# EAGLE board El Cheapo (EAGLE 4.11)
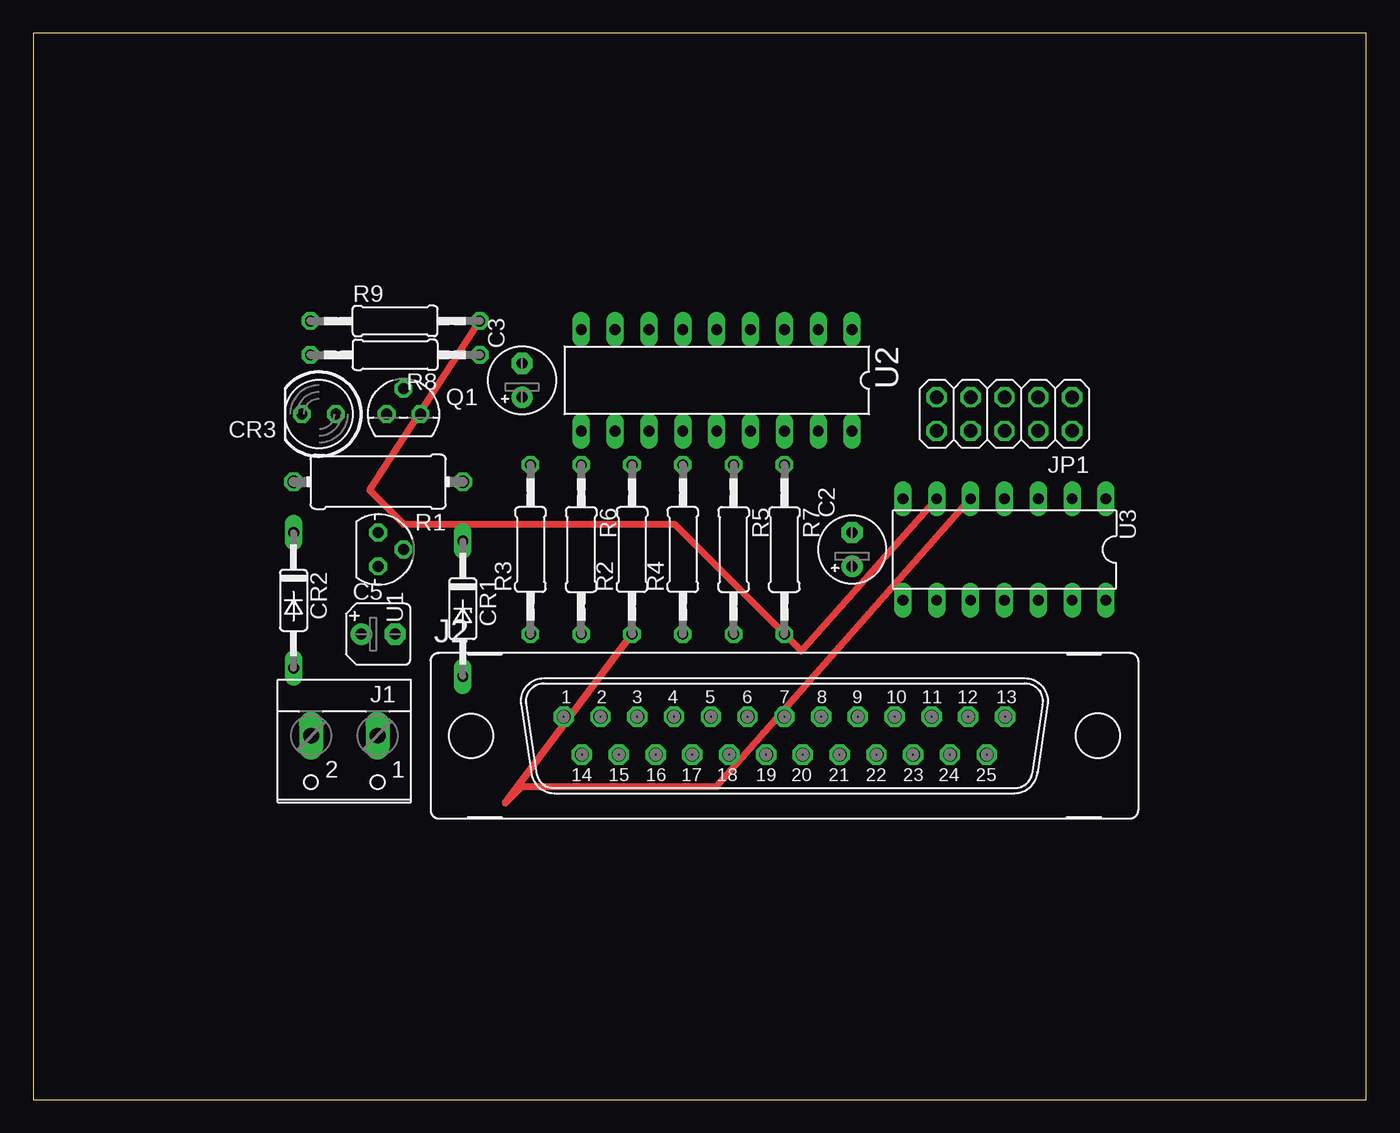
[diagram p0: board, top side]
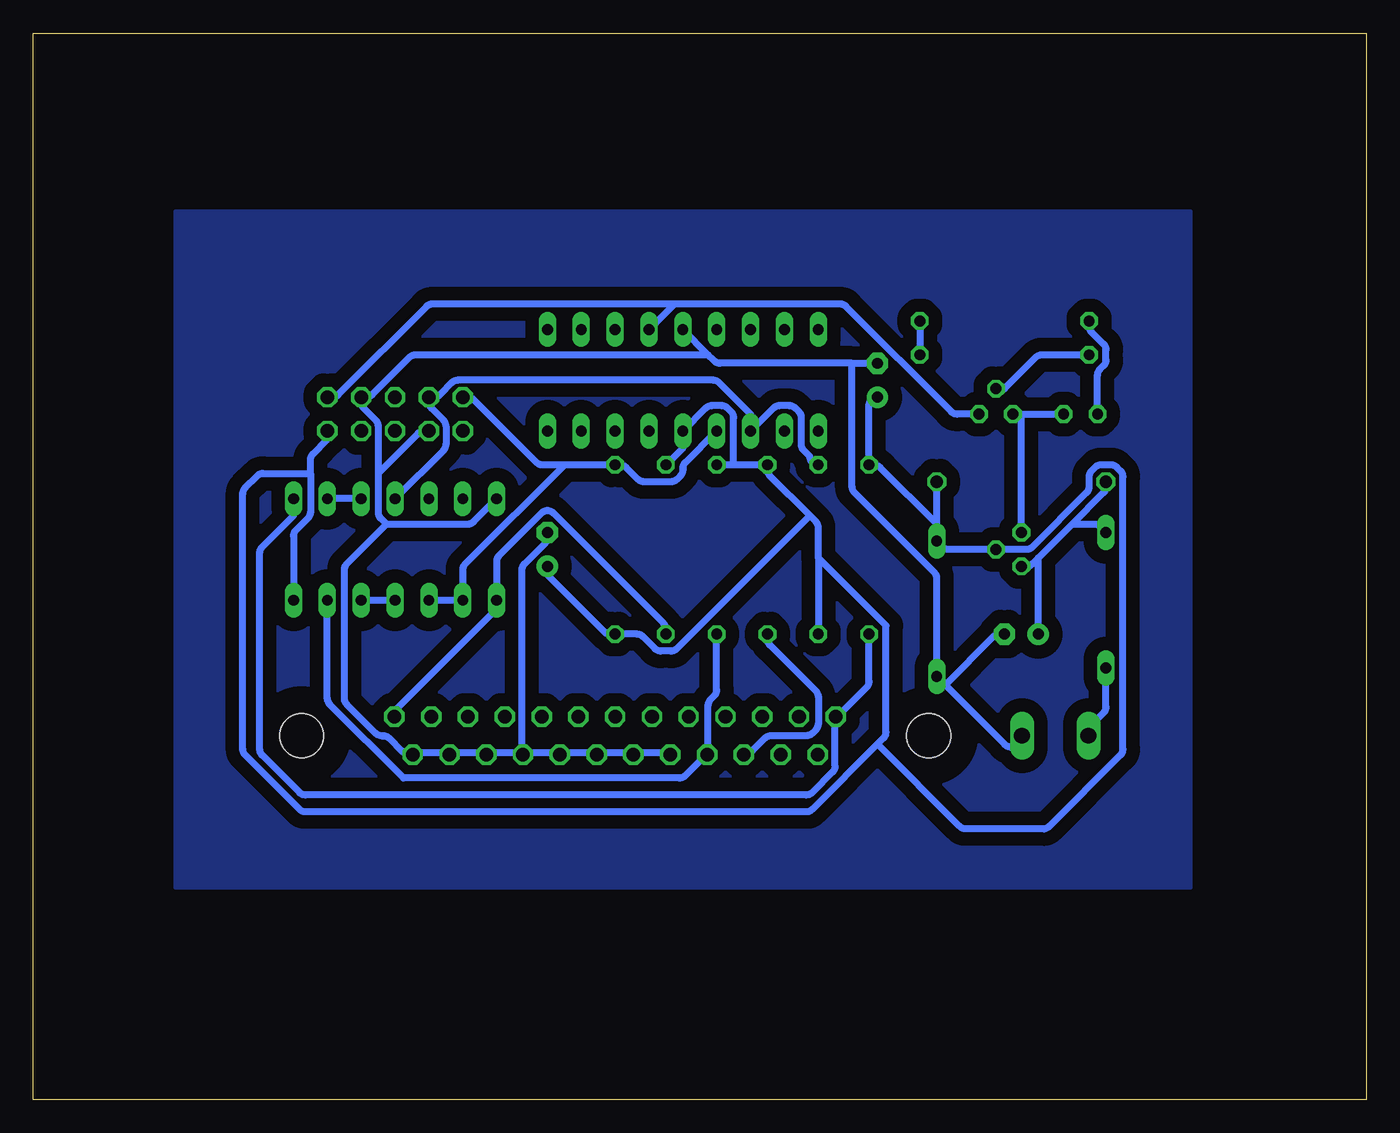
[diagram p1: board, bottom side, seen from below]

Size 100 x 80 mm. Coordinates in mm from the lower left corner, seen from the top.
Outline: 0,0 100,0 100,80 0,80 0,0
Copper layers (1*16): Top 0.035mm / dielectric 1.5mm / Bottom 0.035mm
Design rules "default": minimum track width 20mil, minimum drill 10mil, track to track 10mil, track to pad 10mil, pad to pad 10mil, via to via 8mil, smd to smd 8mil, copper to edge 40mil, drill to drill 8mil, minimum pad ring 10mil, minimum via ring 8mil, stop-mask expansion 4mil, vias tented up to drill 0mil, thermal gap 10mil

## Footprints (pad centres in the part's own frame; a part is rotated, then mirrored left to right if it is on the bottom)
E2,5-5 = drill 0.813 pad 1.6 round: + -1.27,0 | drill 0.813 pad 1.6 octagon: - 1.27,0
B45181A = drill 0.813 pad 1.6 round: + -1.27,0 | drill 0.813 pad 1.6 octagon: - 1.27,0
DO35Z10 = drill 0.813 long: A 5.08,0; C -5.08,0
DO35-10 = drill 0.813 long: A 5.08,0; C -5.08,0
LED5MM = drill 0.813 octagon: A -1.27,0; K 1.27,0
W237-102 = drill 1.194 long: 1 -2.5,-1.27; 2 2.5,-1.27
M25V = drill 1.016 octagon: 1 -16.561,1.422; 2 -13.792,1.422; 3 -11.049,1.422; 4 -8.28,1.422; 5 -5.512,1.422; 6 -2.769,1.422; 7 0,1.422; 8 2.769,1.422; 9 5.512,1.422; 10 8.28,1.422; 11 11.049,1.422; 12 13.792,1.422; 13 16.561,1.422; 14 -15.189,-1.422; 15 -12.421,-1.422; 16 -9.652,-1.422; 17 -6.909,-1.422; 18 -4.14,-1.422; 19 -1.372,-1.422; 20 1.372,-1.422; 21 4.14,-1.422; 22 6.909,-1.422; 23 9.652,-1.422; 24 12.421,-1.422; 25 15.189,-1.422 | hole 3.302: 23.52,0; -23.52,0
2X05 = drill 1.016 octagon: 1 -5.08,-1.27; 2 -5.08,1.27; 3 -2.54,-1.27; 4 -2.54,1.27; 5 0,-1.27; 6 0,1.27; 7 2.54,-1.27; 8 2.54,1.27; 9 5.08,-1.27; 10 5.08,1.27
TO92 = drill 0.813 octagon: 1 1.27,0; 2 0,1.905; 3 -1.27,0
0411/12 = drill 0.914 octagon: 1 -6.35,0; 2 6.35,0
0207/12 = drill 0.813 octagon: 1 -6.35,0; 2 6.35,0
78LXX = drill 0.813 octagon: GND 0,1.905; IN 1.27,0; OUT -1.27,0
DIL18 = drill 0.813 long: 1 -10.16,-3.81; 2 -7.62,-3.81; 3 -5.08,-3.81; 4 -2.54,-3.81; 5 0,-3.81; 6 2.54,-3.81; 7 5.08,-3.81; 8 7.62,-3.81; 9 10.16,-3.81; 10 10.16,3.81; 11 7.62,3.81; 12 5.08,3.81; 13 2.54,3.81; 14 0,3.81; 15 -2.54,3.81; 16 -5.08,3.81; 17 -7.62,3.81; 18 -10.16,3.81
DIL14 = drill 0.813 long: 1 -7.62,-3.81; 2 -5.08,-3.81; 3 -2.54,-3.81; 4 0,-3.81; 5 2.54,-3.81; 6 5.08,-3.81; 7 7.62,-3.81; 8 7.62,3.81; 9 5.08,3.81; 10 2.54,3.81; 11 0,3.81; 12 -2.54,3.81; 13 -5.08,3.81; 14 -7.62,3.81

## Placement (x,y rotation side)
C2  0.01uF  [E2,5-5]  61.43,41.27 90 top
C3  0.01uF  [E2,5-5]  36.66,53.97 90 top
C5  10u 35V  [B45181A]  25.87,34.92 0 top
CR1  ZPD  [DO35Z10]  32.22,36.83 270 top
CR2  1N4148  [DO35-10]  19.52,37.46 270 top
CR3  [LED5MM]  21.42,51.43 180 top
J1  [W237-102]  23.33,26.03 180 top
J2  [M25V]  56.35,27.3 0 top
JP1  [2X05]  72.86,51.43 180 top
Q1  2N3906  [TO92]  27.77,51.43 0 top
R1  180 1W  [0411/12]  25.87,46.35 180 top
R2  10K  [0207/12]  44.92,41.27 90 top
R3  10K  [0207/12]  37.3,41.27 90 top
R4  10K  [0207/12]  48.73,41.27 90 top
R5  10K  [0207/12]  52.54,41.27 270 top
R6  10K  [0207/12]  41.11,41.27 270 top
R7  10K  [0207/12]  56.35,41.27 270 top
R8  10K  [0207/12]  27.14,55.88 180 top
R9  2.2K  [0207/12]  27.14,58.41 0 top
U1  [78LXX]  25.87,41.27 270 top
U2  18 Pin Socket  [DIL18]  51.27,53.97 180 top
U3  74LS05N  [DIL14]  72.86,41.27 180 top

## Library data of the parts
C2 C3 C5 R1-R9 = rcl
CR1 CR2 = diode
CR3 = led
J1 = con-wago-500
J2 = con-subd
JP1 = pinhead
Q1 = transistor-pnp
U1 = v-reg
U2 = microchip
U3 = 74xx-us

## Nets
GND: C2.- C3.- C5.- CR1.A J1.1 J2.18 J2.19 J2.20 J2.21 J2.22 J2.23 J2.24 J2.25 JP1.3 JP1.8 U2.5 U3.7
N$1: U3.2 U3.3
N$2: C5.+ CR2.C R1.2 U1.IN
N$3: CR3.A Q1.3 U1.OUT
N$4: J2.1 R3.1 U3.1
N$6: CR2.A J1.2
N$7: CR3.K R9.1
N$8: R8.1 R9.2 U3.6
N$9: Q1.2 R8.2
N$10: J2.16 R2.1 U3.5
N$12: J2.17 R4.1 U3.13
N$13: U3.11 U3.12
N$14: J2.13 R5.2 U3.8
N$15: JP1.1 Q1.1 U2.4
RB6: JP1.7 R6.1 U2.12 U3.4
RB7: JP1.9 R7.1 U2.13 U3.9 U3.10
VCC: C2.+ C3.+ CR1.C JP1.2 R1.1 R2.2 R3.2 R4.2 R5.1 R6.2 R7.2 U1.GND U2.14 U3.14

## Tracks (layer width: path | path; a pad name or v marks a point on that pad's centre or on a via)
GND
  Bottom 0.508: J2.18 52.54,26.03 54.45,26.03 J2.19 55.71,26.03 56.98,26.03 J2.20 58.25,26.03 60.16,26.03 J2.21 60.8,26.03 62.7,26.03 J2.22 | C2.- 61.43,42.17 arc45 61.62,41.72 63.15,40.19 arc-45 63.34,39.74 63.34,26.03 J2.22 | J2.22 63.97,26.03 65.88,26.03 J2.23 66.51,26.03 68.41,26.03 J2.24 69.05,26.03 70.95,26.03 J2.25 72.05,25.99 arc32 72.36,26.16 73.31,27.11 arc-45 73.76,27.3 73.87,27.3 arc45 74.32,27.49 76.48,29.65 arc45 76.67,30.1 76.67,39.74 arc45 76.48,40.19 73.5,43.18 | 74.13,46.98 74.13,44.07 arc-45 73.94,43.62 73.5,43.18 | 73.5,43.18 67.41,43.18 arc-45 66.96,43.36 U3.7 | 74.13,46.98 71.14,49.97 arc45 70.69,50.16 JP1.8 | 74.13,46.98 74.13,50.53 arc-45 74.32,50.98 75.21,51.88 arc45 75.4,52.33 JP1.3 75.03,52.7 arc-45 74.58,52.89 71.78,55.69 arc45 71.33,55.88 49.37,55.88 | J1.1 26.1,26.79 arc107 27.11,26.64 31.58,31.11 | 31.58,31.11 27.96,34.73 arc45 27.51,34.92 C5.- | 31.58,31.11 CR1.A 32.22,39.1 arc-45 32.41,39.55 38.38,45.53 arc45 38.57,45.98 38.57,55.24 | 38.57,55.24 48.47,55.24 arc45 48.92,55.43 49.37,55.88 | 49.37,55.88 U2.5 | 38.57,55.24 C3.-
N$1
  Bottom 0.508: U3.3 U3.2
N$2
  Bottom 0.508: 24.6,40.64 22.06,43.18 | 24.6,40.64 25.05,40.19 arc45 25.5,40 U1.IN | 22.06,43.18 19.71,45.53 arc-45 19.52,45.98 R1.2 | 22.06,43.18 20.42,43.18 arc45 19.97,42.99 CR2.C | C5.+ 24.6,40.64
N$3
  Bottom 0.508: U1.OUT 25.87,51.43 | 25.87,51.43 CR3.A | 25.87,51.43 Q1.3
N$4
  Bottom 0.508: R3.1 37.3,31.37 arc45 37.49,30.92 39.2,29.2 J2.1 39.81,28.67 arc-18 39.84,28.47 39.84,25.02 arc45 40.03,24.57 41.56,23.04 arc45 42.01,22.86 79.58,22.86 arc45 80.03,23.04 82.83,25.84 arc45 83.02,26.29 83.02,41.01 arc45 82.83,41.46 80.48,43.81 U3.1
N$6
  Bottom 0.508: CR2.A 19.52,29.47 arc45 19.71,29.02 20.09,28.64 arc-17 20.2,28.49 J1.2
N$7
  Bottom 0.508: CR3.K 20.15,54.34 arc45 19.97,54.79 19.71,55.05 arc-45 19.52,55.5 19.52,56.25 arc-45 19.71,56.7 20.6,57.59 arc45 20.79,58.04 R9.1
N$8
  Top 0.508: U3.6 57.62,33.65 48.09,43.18 27.77,43.18 25.23,45.72 R9.2
  Bottom 0.508: R9.2 R8.1
N$9
  Bottom 0.508: R8.2 24.34,55.88 arc-45 24.79,55.69 27.14,53.34 Q1.2
N$10
  Top 0.508: U3.5 51.27,23.49 36.66,23.49 35.39,22.22 R2.1
  Bottom 0.508: R2.1 44.92,34.55 arc-45 44.73,34.1 41.3,30.66 arc45 41.11,30.21 41.11,28.2 arc45 41.3,27.75 41.56,27.49 arc45 42.01,27.3 44.66,27.3 arc-45 45.11,27.11 46.08,26.14 arc28 46.34,25.98 J2.16
N$12
  Bottom 0.508: R4.1 48.73,30.74 arc45 48.92,30.29 49.18,30.03 arc-45 49.37,29.58 49.37,26.18 arc27 49.43,25.9 J2.17 49.98,25.41 arc-4 50.02,25.38 51.08,24.31 arc45 51.53,24.12 72.22,24.12 77.75,29.65 arc45 77.94,30.1 U3.13
N$13
  Bottom 0.508: U3.11 U3.12
N$14
  Bottom 0.508: R5.2 52.54,35.29 arc-45 52.73,35.74 60.98,44 arc-90 61.88,44 65.05,40.82 arc-45 65.24,40.37 U3.8 65.24,36.83 72.86,29.2 J2.13
N$15
  Bottom 0.508: 51.91,59.69 39.47,59.69 arc45 39.02,59.5 31.14,51.62 arc-45 30.69,51.43 Q1.1 | 51.91,59.69 U2.4 | 51.91,59.69 70.06,59.69 arc-45 70.51,59.5 77.12,52.89 arc45 77.57,52.7 JP1.1
N$18
  pour Bottom (isolate 1.016): 13.17,66.67 89.37,66.67 89.37,15.87 13.17,15.87
RB6
  Bottom 0.508: R6.1 arc90 41.74,48.26 42.19,48.7 arc45 42.38,49.15 42.38,51.17 arc-45 42.57,51.62 42.83,51.88 arc-45 43.28,52.07 44.02,52.07 arc-45 44.47,51.88 U2.12 46.19,51.43 48.54,53.78 arc-45 48.99,53.97 68.15,53.97 arc-45 68.6,53.78 69.5,52.89 arc45 69.95,52.7 JP1.7 70.32,52.33 arc-45 70.13,51.88 69.24,50.98 arc45 69.05,50.53 69.05,49.15 arc45 69.24,48.7 U3.4
RB7
  Bottom 0.508: U3.10 U3.9 67.78,39.74 arc45 67.59,40.19 60.16,47.62 | 60.16,47.62 R7.1 55.98,47.62 arc45 55.53,47.43 54.63,46.54 arc-45 54.18,46.35 52.17,46.35 arc-45 51.72,46.54 51.46,46.8 arc-45 51.27,47.25 51.27,47.36 arc45 51.08,47.81 U2.13 | 60.16,47.62 61.8,47.62 arc45 62.25,47.81 66.96,52.51 arc-45 67.41,52.7 JP1.9
VCC
  Bottom 0.508: C3.+ arc-90 37.3,52.07 R3.2 36.93,47.62 arc45 36.48,47.43 32.22,43.18 | 32.22,43.18 R1.1 | 32.22,43.18 CR1.C 31.77,41.46 arc-45 31.32,41.27 U1.GND 25.5,41.27 arc-45 25.05,41.46 20.98,45.53 arc-45 20.79,45.98 20.79,46.72 arc45 20.6,47.17 20.34,47.43 arc45 19.89,47.62 19.15,47.62 arc45 18.7,47.43 18.44,47.17 arc45 18.25,46.72 18.25,26.29 arc45 18.44,25.84 23.78,20.5 arc45 24.23,20.31 30.05,20.31 arc45 30.5,20.5 36.66,26.66 | 79.21,46.98 79.21,47.99 arc45 79.02,48.44 77.94,49.53 JP1.2 | 79.21,46.98 79.21,44.07 arc45 79.4,43.62 80.29,42.73 arc-45 80.48,42.28 U3.14 | C2.+ 61.43,39.63 arc-45 61.24,39.18 57.17,35.11 arc-45 56.72,34.92 R7.2 54.71,34.92 arc45 54.26,34.73 53.36,33.84 arc-45 52.91,33.65 52.17,33.65 arc-45 51.72,33.84 41.74,43.81 | R5.1 51.27,48.89 U2.14 49.55,51.88 arc45 49.1,52.07 48.36,52.07 arc45 47.91,51.88 47.65,51.62 arc45 47.46,51.17 47.46,47.62 | 41.11,40.64 41.11,42.91 arc-45 41.3,43.36 41.74,43.81 | 41.11,40.64 R6.2 | 41.74,43.81 44.73,46.8 arc45 44.92,47.25 R2.2 47.46,47.62 | 47.46,47.62 R4.2 | 79.21,46.98 82.76,46.98 arc-45 83.21,46.8 84.1,45.9 arc-45 84.29,45.45 84.29,26.29 arc-45 84.1,25.84 80.03,21.77 arc-45 79.58,21.58 42.01,21.58 arc-45 41.56,21.77 36.66,26.66 | 36.66,26.66 36.22,27.11 arc-45 36.03,27.56 36.03,35.55 41.11,40.64

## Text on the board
Document: See http://www.myke.com/elcheapo.htm for documentation and software | 2x5 (10 Pin) Header ADDED for ICSP off board | J1 changed from 2.5mm to 2 POS Screw clamp on 0.20 centers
